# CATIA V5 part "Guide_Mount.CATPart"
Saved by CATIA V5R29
Part number: Guide_Mount_02
Source: Unknown
Bounding box of the stored display mesh (mm): x -50 to 50, y 0 to 30, z -45 to 45
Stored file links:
  C:\가치같이\SmartFactory_BoxErectorConveyor\Boxing(under)\Guide_Mount.CATPart
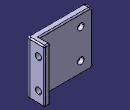
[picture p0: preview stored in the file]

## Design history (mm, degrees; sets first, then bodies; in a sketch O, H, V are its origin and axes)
Body1 (main body)
  Solid1 "PartBody": solid without history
